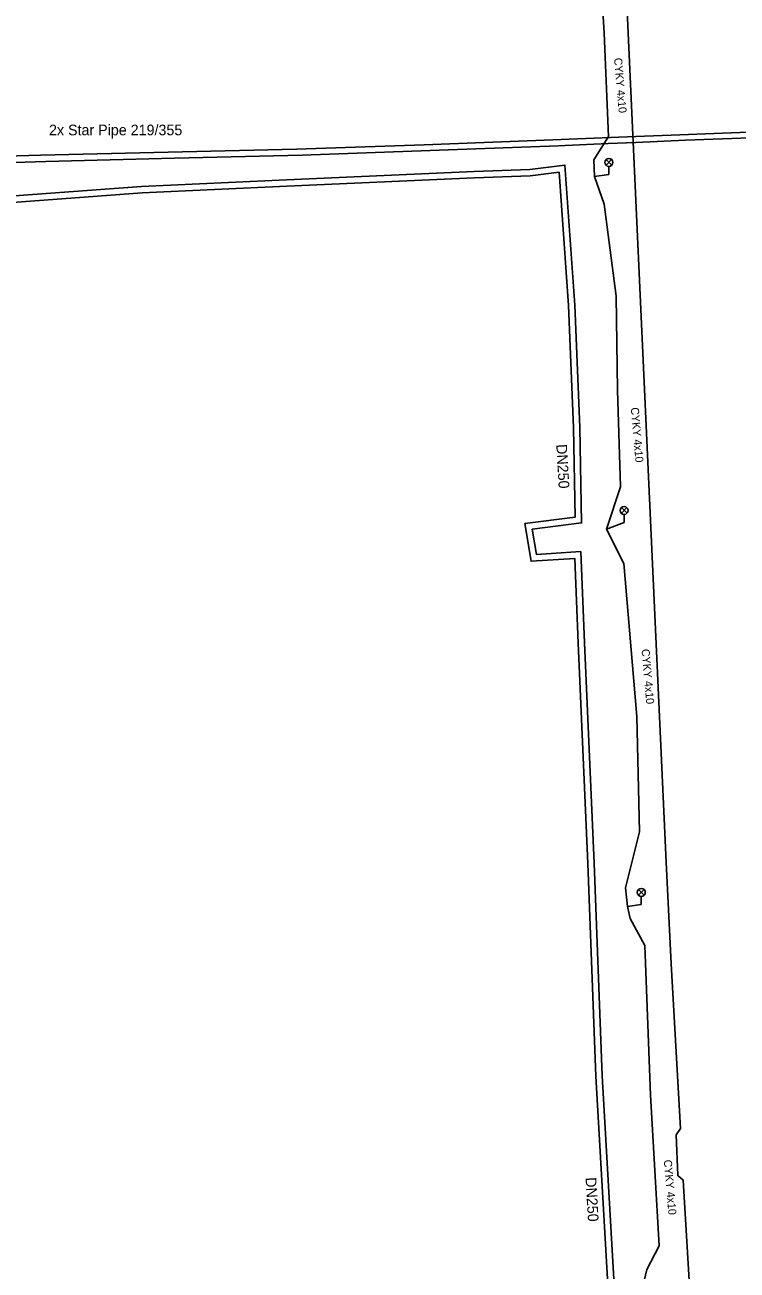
# Model space of a CAD drawing. Extents: x -736399 to -735926, y -1118992 to -1118244.
# Drawn here: x -736294.2 to -736227.5, y -1118790.4 to -1118673.7 of the extents above; entities that cross this region are included whole.
import ezdxf

# ---------------------------------------------------------------- set-up
doc = ezdxf.new("R2010")
doc.units = 0
for name, color, linetype in [('Kabelové vedení VO', 7, 'Continuous'), ('Osa trasy kynety', 7, 'Continuous'), ('Podz_ teplovodní potrubí', 7, 'Continuous'), ('Popis teplovodu', 7, 'Continuous'), ('Popis VO', 7, 'Continuous'), ('Povrchové znaky VO', 7, 'Continuous')]:
    doc.layers.add(name, color=color, linetype=linetype)

msp = doc.modelspace()

# ---------------------------------------------------------------- linework, layer by layer
at = {"layer": 'Kabelové vedení VO'}
for points in [[(-736240.82, -1118687.87), (-736240.88, -1118686.33), (-736239.51, -1118684.12), (-736239.91, -1118674.43), (-736240.85, -1118658.74), (-736241.83, -1118655.57), (-736242.31, -1118654.5), (-736240.99, -1118654.38)], [(-736239.69, -1118720.93), (-736238.38, -1118716.97), (-736238.67, -1118707.9), (-736238.8, -1118699.11), (-736239.91, -1118690.48), (-736240.82, -1118687.87), (-736239.47, -1118687.68)], [(-736237.71, -1118756.3), (-736237.91, -1118754.56), (-736236.6, -1118749.3), (-736236.86, -1118738.49), (-736238.06, -1118724.15), (-736239.69, -1118720.93), (-736238.04, -1118720.31)], [(-736236.37, -1118792.35), (-736235.92, -1118790.35), (-736234.77, -1118788.12), (-736235.57, -1118774.01), (-736236.11, -1118759.98), (-736237.49, -1118757.44), (-736237.71, -1118756.3), (-736236.43, -1118756.11)]]:
    msp.add_lwpolyline(points, dxfattribs=at)
at = {"layer": 'Osa trasy kynety'}
for points in [[(-736234.1, -1118752.15), (-736238.64, -1118653.26), (-736238.95, -1118644.76), (-736240.19, -1118616.12), (-736243.35, -1118610.17), (-736239.41, -1118528.25)], [(-736230.34, -1118817.96), (-736232.5, -1118781.95), (-736233.01, -1118781.54), (-736233.17, -1118777.7), (-736232.75, -1118777.13), (-736233.63, -1118761.7), (-736234.1, -1118752.15)]]:
    msp.add_lwpolyline(points, dxfattribs=at)
at = {"layer": 'Podz_ teplovodní potrubí'}
for points in [[(-736220.79, -1118683.52), (-736232.82, -1118683.98), (-736236.94, -1118684.14), (-736239.32, -1118684.24), (-736244.73, -1118684.43), (-736256.78, -1118684.91), (-736268.74, -1118685.31), (-736280.76, -1118685.61), (-736292.72, -1118685.88), (-736297.11, -1118686.01), (-736304.76, -1118686.32), (-736315.56, -1118686.84), (-736316.72, -1118686.9), (-736328.75, -1118687.52), (-736336.07, -1118687.95), (-736336.97, -1118688), (-736340.11, -1118688.18), (-736341.02, -1118688.2)], [(-736340.95, -1118688.75), (-736340.13, -1118688.68), (-736336.91, -1118688.54), (-736335.87, -1118688.47), (-736328.18, -1118688.08), (-736316.17, -1118687.48), (-736315.56, -1118687.45), (-736304.21, -1118686.89), (-736297.1, -1118686.63), (-736292.21, -1118686.47), (-736280.17, -1118686.16), (-736268.21, -1118685.87), (-736256.2, -1118685.43), (-736244.23, -1118685.01), (-736239.55, -1118684.8), (-736236.95, -1118684.68), (-736232.28, -1118684.49), (-736220.19, -1118684.03)], [(-736238.53, -1118799.39), (-736240.09, -1118772.19), (-736240.84, -1118752.25), (-736241.75, -1118731.61), (-736242.1, -1118723.04), (-736246.25, -1118723.31), (-736246.65, -1118720.94), (-736242.02, -1118720.35), (-736242.18, -1118711.42), (-736242.65, -1118699.93), (-736243.59, -1118686.81), (-736246.88, -1118687.22), (-736252.09, -1118687.42), (-736269.68, -1118688.18), (-736283.24, -1118688.82), (-736301.55, -1118690.16), (-736300.72, -1118693.75), (-736302.67, -1118694.14), (-736303.35, -1118690.16), (-736309.88, -1118690.08), (-736322.12, -1118690.68), (-736341.98, -1118691.48)], [(-736239.16, -1118798.84), (-736240.69, -1118772.22), (-736241.44, -1118752.27), (-736242.35, -1118731.63), (-736242.67, -1118723.68), (-736246.75, -1118723.94), (-736247.34, -1118720.42), (-736242.63, -1118719.82), (-736242.78, -1118711.44), (-736243.25, -1118699.96), (-736244.14, -1118687.48), (-736246.83, -1118687.82), (-736252.07, -1118688.02), (-736269.65, -1118688.78), (-736283.2, -1118689.42), (-736300.81, -1118690.71), (-736299.99, -1118694.22), (-736303.16, -1118694.85), (-736303.86, -1118690.75), (-736309.87, -1118690.68), (-736322.09, -1118691.28), (-736338.46, -1118691.94), (-736341.32, -1118692.06)]]:
    msp.add_lwpolyline(points, dxfattribs=at)
at = {"layer": 'Povrchové znaky VO'}
for p, q in [((-736239.73, -1118686.82), (-736239.21, -1118686.29)), ((-736239.2, -1118686.81), (-736239.73, -1118686.29)), ((-736239.47, -1118687.68), (-736239.47, -1118686.93)), ((-736238.3, -1118719.45), (-736237.78, -1118718.92)), ((-736237.77, -1118719.45), (-736238.3, -1118718.92)), ((-736238.04, -1118720.31), (-736238.04, -1118719.56)), ((-736236.69, -1118755.25), (-736236.17, -1118754.72)), ((-736236.16, -1118755.25), (-736236.69, -1118754.72)), ((-736236.43, -1118756.11), (-736236.43, -1118755.36))]:
    msp.add_line(p, q, dxfattribs=at)
for centre in [(-736239.47, -1118686.56), (-736238.04, -1118719.19), (-736236.43, -1118754.99)]:
    msp.add_circle(centre, 0.375, dxfattribs=at)

# ---------------------------------------------------------------- texts
at = {"layer": 'Popis teplovodu'}
for s, rotation, p in [('2x Star Pipe 219/355', 0.003, (-736291.92, -1118684.02)), ('DN250', 273.2895, (-736244.4, -1118713)), ('DN250', 273.2895, (-736241.66, -1118781.72))]:
    msp.add_text(s, height=1, rotation=rotation, dxfattribs=at).set_placement(p)
at = {"layer": 'Popis VO'}
for p in [(-736238.99, -1118676.79), (-736237.42, -1118709.55), (-736236.41, -1118732.2), (-736234.33, -1118780.08)]:
    msp.add_text('CYKY 4x10', height=0.75, rotation=275, dxfattribs=at).set_placement(p)

doc.saveas('drawing.dxf')
